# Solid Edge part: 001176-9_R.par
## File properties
Last saved by: morva
Revision: 82
Accuracy: 0.990
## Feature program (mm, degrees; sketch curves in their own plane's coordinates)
body "unnamed Body 1"
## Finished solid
Body 1: solid body, 70 faces, 175 edges, 107 vertices.
  Faces by surface: torus 37, cylinder 23, cone 6, plane 4
  Edges by curve: circle 90, spline 44, line 33, curve on surface 8
Bounding box of the edges (mm; curved faces can reach further): 15.699 x 15.690 x 10.882, from (432.9066, 378.1746, 140.9215) to (448.6055, 393.8641, 151.8037).
Cylindrical faces by radius (mm): R0.5 x9, R3 x9, R7.5 x5
Conical faces (half-angle, radius in mm at the cone's reference point): 45 deg R4 x6
Toroidal faces (ring radius, tube radius in mm): R0.3 r0.2 x19, R3.2 r0.2 x10, R7.3 r0.2 x8
Planar faces by outward normal: oblique 4
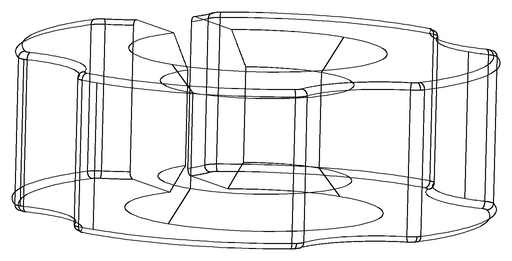
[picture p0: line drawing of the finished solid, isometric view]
